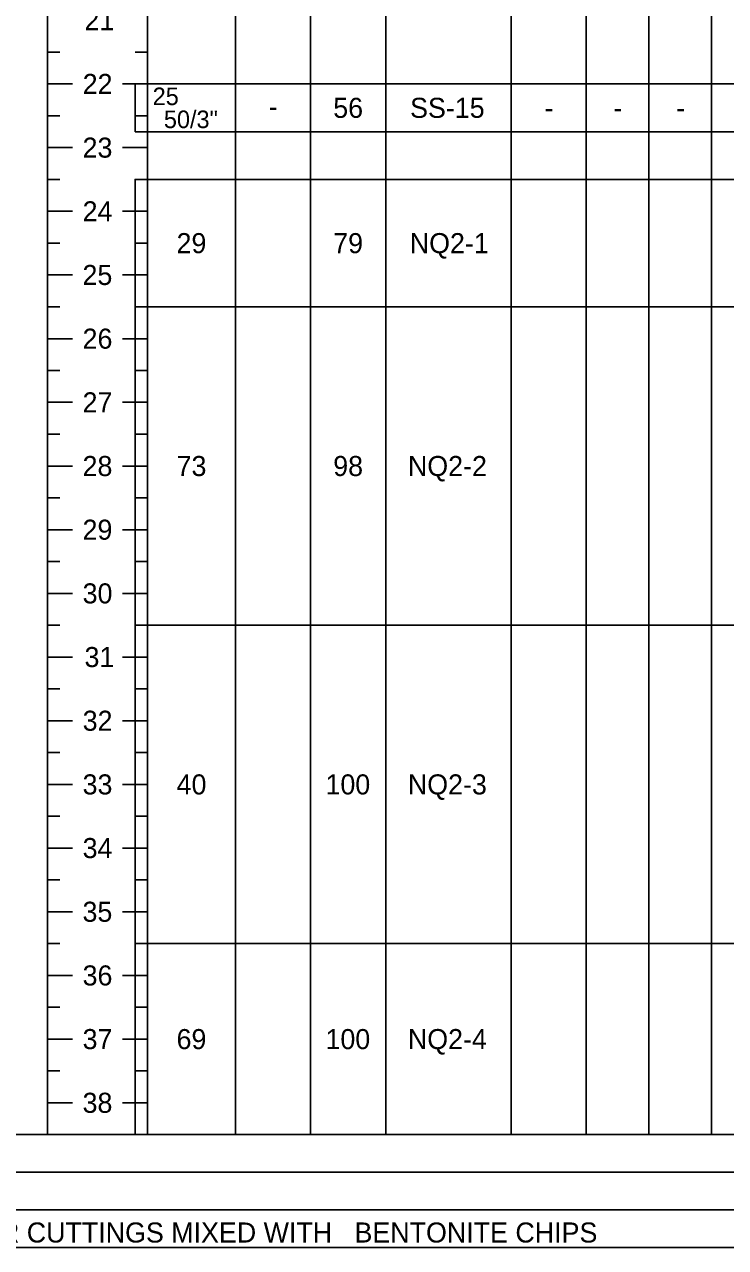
# Model space of a CAD drawing. Extents: x 0 to 0.833, y -0.323 to 0.608.
# Drawn here: x 0.3715 to 0.6046, y -0.3233 to 0.0833 of the extents above; entities that cross this region are included whole.
import ezdxf

# ---------------------------------------------------------------- set-up
doc = ezdxf.new("R2010")
doc.units = 0

msp = doc.modelspace()

# ---------------------------------------------------------------- linework, layer by layer
for points in [[(0, -0.32328), (0.83333, -0.32328), (0.83333, 0.60833), (0, 0.60833)], [(0.40833, 0.04762), (0.4125, 0.04762), (0.4125, 0.0635), (0.40833, 0.0635)], [(0.40833, -0.01058), (0.4125, -0.01058), (0.4125, 0.03175), (0.40833, 0.03175)], [(0.40833, -0.11642), (0.4125, -0.11642), (0.4125, -0.01058), (0.40833, -0.01058)], [(0.40833, -0.22225), (0.4125, -0.22225), (0.4125, -0.11642), (0.40833, -0.11642)], [(0.40833, -0.28575), (0.4125, -0.28575), (0.4125, -0.22225), (0.40833, -0.22225)]]:
    msp.add_lwpolyline(points, close=True)
for points in [[(0.4125, 0.55417), (0.4125, -0.28575)], [(0.4125, 0.55417), (0.4125, -0.28575)], [(0.44167, 0.55417), (0.44167, -0.28575)], [(0.46667, 0.55417), (0.46667, -0.28575)], [(0.49167, 0.55417), (0.49167, -0.28575)], [(0.53333, 0.55417), (0.53333, -0.28575)], [(0.55833, 0.55417), (0.55833, -0.28575)], [(0.57917, 0.54167), (0.57917, -0.28575)], [(0.6, 0.54167), (0.6, -0.28575)], [(0.37917, 0.52917), (0.37917, -0.28575)], [(0.37917, 0.07408), (0.38333, 0.07408)], [(0.4125, 0.07408), (0.40833, 0.07408)], [(0.37917, 0.0635), (0.3875, 0.0635)], [(0.37917, 0.0635), (0.38333, 0.0635)], [(0.4125, 0.0635), (0.40417, 0.0635)], [(0.40833, 0.0635), (0.40833, 0.04762)], [(0.40833, 0.0635), (0.4125, 0.0635)], [(0.4125, 0.0635), (0.40833, 0.0635)], [(0.4125, 0.0635), (0.44167, 0.0635)], [(0.44167, 0.0635), (0.46667, 0.0635)], [(0.46667, 0.0635), (0.49167, 0.0635)], [(0.49167, 0.0635), (0.53333, 0.0635)], [(0.53333, 0.0635), (0.55833, 0.0635)], [(0.55833, 0.0635), (0.57917, 0.0635)], [(0.57917, 0.0635), (0.6, 0.0635)], [(0.6, 0.0635), (0.62083, 0.0635)], [(0.37917, 0.05292), (0.38333, 0.05292)], [(0.4125, 0.05292), (0.40833, 0.05292)], [(0.40833, 0.04762), (0.4125, 0.04762)], [(0.4125, 0.04762), (0.44167, 0.04762)], [(0.44167, 0.04762), (0.46667, 0.04762)], [(0.46667, 0.04762), (0.49167, 0.04762)], [(0.49167, 0.04762), (0.53333, 0.04762)], [(0.53333, 0.04762), (0.55833, 0.04762)], [(0.55833, 0.04762), (0.57917, 0.04762)], [(0.57917, 0.04762), (0.6, 0.04762)], [(0.6, 0.04762), (0.62083, 0.04762)], [(0.37917, 0.04233), (0.3875, 0.04233)], [(0.37917, 0.04233), (0.38333, 0.04233)], [(0.4125, 0.04233), (0.40417, 0.04233)], [(0.4125, 0.04233), (0.40833, 0.04233)], [(0.37917, 0.03175), (0.38333, 0.03175)], [(0.40833, 0.03175), (0.40833, -0.01058)], [(0.40833, 0.03175), (0.4125, 0.03175)], [(0.4125, 0.03175), (0.40833, 0.03175)], [(0.4125, 0.03175), (0.44167, 0.03175)], [(0.44167, 0.03175), (0.46667, 0.03175)], [(0.46667, 0.03175), (0.49167, 0.03175)], [(0.49167, 0.03175), (0.53333, 0.03175)], [(0.53333, 0.03175), (0.55833, 0.03175)], [(0.55833, 0.03175), (0.57917, 0.03175)], [(0.57917, 0.03175), (0.6, 0.03175)], [(0.6, 0.03175), (0.62083, 0.03175)], [(0.37917, 0.02117), (0.3875, 0.02117)], [(0.37917, 0.02117), (0.38333, 0.02117)], [(0.4125, 0.02117), (0.40417, 0.02117)], [(0.4125, 0.02117), (0.40833, 0.02117)], [(0.37917, 0.01058), (0.38333, 0.01058)], [(0.4125, 0.01058), (0.40833, 0.01058)], [(0.37917, 0), (0.3875, 0)], [(0.37917, 0), (0.38333, 0)], [(0.4125, 0), (0.40417, 0)], [(0.4125, 0), (0.40833, 0)], [(0.37917, -0.01058), (0.38333, -0.01058)], [(0.40833, -0.01058), (0.4125, -0.01058)], [(0.40833, -0.01058), (0.40833, -0.11642)], [(0.40833, -0.01058), (0.4125, -0.01058)], [(0.4125, -0.01058), (0.40833, -0.01058)], [(0.4125, -0.01058), (0.44167, -0.01058)], [(0.44167, -0.01058), (0.46667, -0.01058)], [(0.46667, -0.01058), (0.49167, -0.01058)], [(0.49167, -0.01058), (0.53333, -0.01058)], [(0.53333, -0.01058), (0.55833, -0.01058)], [(0.55833, -0.01058), (0.57917, -0.01058)], [(0.57917, -0.01058), (0.6, -0.01058)], [(0.6, -0.01058), (0.62083, -0.01058)], [(0.37917, -0.02117), (0.3875, -0.02117)], [(0.37917, -0.02117), (0.38333, -0.02117)], [(0.4125, -0.02117), (0.40417, -0.02117)], [(0.4125, -0.02117), (0.40833, -0.02117)], [(0.37917, -0.03175), (0.38333, -0.03175)], [(0.4125, -0.03175), (0.40833, -0.03175)], [(0.37917, -0.04233), (0.3875, -0.04233)], [(0.37917, -0.04233), (0.38333, -0.04233)], [(0.4125, -0.04233), (0.40417, -0.04233)], [(0.4125, -0.04233), (0.40833, -0.04233)], [(0.37917, -0.05292), (0.38333, -0.05292)], [(0.4125, -0.05292), (0.40833, -0.05292)], [(0.37917, -0.0635), (0.3875, -0.0635)], [(0.37917, -0.0635), (0.38333, -0.0635)], [(0.4125, -0.0635), (0.40417, -0.0635)], [(0.4125, -0.0635), (0.40833, -0.0635)], [(0.37917, -0.07408), (0.38333, -0.07408)], [(0.4125, -0.07408), (0.40833, -0.07408)], [(0.37917, -0.08467), (0.3875, -0.08467)], [(0.37917, -0.08467), (0.38333, -0.08467)], [(0.4125, -0.08467), (0.40417, -0.08467)], [(0.4125, -0.08467), (0.40833, -0.08467)], [(0.37917, -0.09525), (0.38333, -0.09525)], [(0.4125, -0.09525), (0.40833, -0.09525)], [(0.37917, -0.10583), (0.3875, -0.10583)], [(0.37917, -0.10583), (0.38333, -0.10583)], [(0.4125, -0.10583), (0.40417, -0.10583)], [(0.4125, -0.10583), (0.40833, -0.10583)], [(0.37917, -0.11642), (0.38333, -0.11642)], [(0.40833, -0.11642), (0.4125, -0.11642)], [(0.40833, -0.11642), (0.40833, -0.22225)], [(0.40833, -0.11642), (0.4125, -0.11642)], [(0.4125, -0.11642), (0.40833, -0.11642)], [(0.4125, -0.11642), (0.44167, -0.11642)], [(0.44167, -0.11642), (0.46667, -0.11642)], [(0.46667, -0.11642), (0.49167, -0.11642)], [(0.49167, -0.11642), (0.53333, -0.11642)], [(0.53333, -0.11642), (0.55833, -0.11642)], [(0.55833, -0.11642), (0.57917, -0.11642)], [(0.57917, -0.11642), (0.6, -0.11642)], [(0.6, -0.11642), (0.62083, -0.11642)], [(0.37917, -0.127), (0.3875, -0.127)], [(0.37917, -0.127), (0.38333, -0.127)], [(0.4125, -0.127), (0.40417, -0.127)], [(0.4125, -0.127), (0.40833, -0.127)], [(0.37917, -0.13758), (0.38333, -0.13758)], [(0.4125, -0.13758), (0.40833, -0.13758)], [(0.37917, -0.14817), (0.3875, -0.14817)], [(0.37917, -0.14817), (0.38333, -0.14817)], [(0.4125, -0.14817), (0.40417, -0.14817)], [(0.4125, -0.14817), (0.40833, -0.14817)], [(0.37917, -0.15875), (0.38333, -0.15875)], [(0.4125, -0.15875), (0.40833, -0.15875)], [(0.37917, -0.16933), (0.3875, -0.16933)], [(0.37917, -0.16933), (0.38333, -0.16933)], [(0.4125, -0.16933), (0.40417, -0.16933)], [(0.4125, -0.16933), (0.40833, -0.16933)], [(0.37917, -0.17992), (0.38333, -0.17992)], [(0.4125, -0.17992), (0.40833, -0.17992)], [(0.37917, -0.1905), (0.3875, -0.1905)], [(0.37917, -0.1905), (0.38333, -0.1905)], [(0.4125, -0.1905), (0.40417, -0.1905)], [(0.4125, -0.1905), (0.40833, -0.1905)], [(0.37917, -0.20108), (0.38333, -0.20108)], [(0.4125, -0.20108), (0.40833, -0.20108)], [(0, -0.21078), (0, -0.32328), (0.83333, -0.32328), (0.83333, -0.21078)], [(0.37917, -0.21167), (0.3875, -0.21167)], [(0.37917, -0.21167), (0.38333, -0.21167)], [(0.4125, -0.21167), (0.40417, -0.21167)], [(0.4125, -0.21167), (0.40833, -0.21167)], [(0.37917, -0.22225), (0.38333, -0.22225)], [(0.40833, -0.22225), (0.4125, -0.22225)], [(0.40833, -0.22225), (0.40833, -0.28575)], [(0.40833, -0.22225), (0.4125, -0.22225)], [(0.4125, -0.22225), (0.40833, -0.22225)], [(0.4125, -0.22225), (0.44167, -0.22225)], [(0.44167, -0.22225), (0.46667, -0.22225)], [(0.46667, -0.22225), (0.49167, -0.22225)], [(0.49167, -0.22225), (0.53333, -0.22225)], [(0.53333, -0.22225), (0.55833, -0.22225)], [(0.55833, -0.22225), (0.57917, -0.22225)], [(0.57917, -0.22225), (0.6, -0.22225)], [(0.6, -0.22225), (0.62083, -0.22225)], [(0.37917, -0.23283), (0.3875, -0.23283)], [(0.37917, -0.23283), (0.38333, -0.23283)], [(0.4125, -0.23283), (0.40417, -0.23283)], [(0.4125, -0.23283), (0.40833, -0.23283)], [(0.37917, -0.24342), (0.38333, -0.24342)], [(0.4125, -0.24342), (0.40833, -0.24342)], [(0.37917, -0.254), (0.3875, -0.254)], [(0.37917, -0.254), (0.38333, -0.254)], [(0.4125, -0.254), (0.40417, -0.254)], [(0.4125, -0.254), (0.40833, -0.254)], [(0.37917, -0.26458), (0.38333, -0.26458)], [(0.4125, -0.26458), (0.40833, -0.26458)], [(0.37917, -0.27517), (0.3875, -0.27517)], [(0.37917, -0.27517), (0.38333, -0.27517)], [(0.4125, -0.27517), (0.40417, -0.27517)], [(0.4125, -0.27517), (0.40833, -0.27517)], [(0.33333, -0.28575), (0.37917, -0.28575)], [(0.37917, -0.28575), (0.4125, -0.28575)], [(0.37917, -0.28575), (0.38333, -0.28575)], [(0.37917, -0.28575), (0.39583, -0.28575)], [(0.4125, -0.28575), (0.39583, -0.28575)], [(0.40833, -0.28575), (0.4125, -0.28575)], [(0.40833, -0.28575), (0.4125, -0.28575)], [(0.4125, -0.28575), (0.40833, -0.28575)], [(0.4125, -0.28575), (0.44167, -0.28575)], [(0.44167, -0.28575), (0.46667, -0.28575)], [(0.46667, -0.28575), (0.49167, -0.28575)], [(0.49167, -0.28575), (0.53333, -0.28575)], [(0.53333, -0.28575), (0.55833, -0.28575)], [(0.55833, -0.28575), (0.57917, -0.28575)], [(0.57917, -0.28575), (0.6, -0.28575)], [(0.6, -0.28575), (0.62083, -0.28575)], [(0, -0.29828), (0.83333, -0.29828)], [(0, -0.31078), (0.83333, -0.31078)]]:
    msp.add_lwpolyline(points)

# ---------------------------------------------------------------- texts
for s, height, p in [('21', 0.006667, (0.39151, 0.08133)), ('22', 0.006667, (0.3909, 0.06017)), ('25', 0.005833, (0.41417, 0.05647)), ('56', 0.006667, (0.4742, 0.05223)), ('SS-15', 0.006667, (0.49974, 0.05223)), ('50/3"', 0.005833, (0.4179, 0.04882)), ('-', 0.00667, (0.45276, 0.05265)), ('-', 0.00667, (0.54443, 0.05223)), ('-', 0.00667, (0.56734, 0.05223)), ('-', 0.00667, (0.58818, 0.05223)), ('23', 0.006667, (0.39087, 0.039)), ('24', 0.006667, (0.39088, 0.01783)), ('29', 0.006667, (0.42211, 0.00725)), ('79', 0.006667, (0.47419, 0.00725)), ('NQ2-1', 0.006667, (0.49964, 0.00725)), ('25', 0.006667, (0.39084, -0.00333)), ('26', 0.006667, (0.39087, -0.0245)), ('27', 0.006667, (0.39087, -0.04567)), ('28', 0.006667, (0.39086, -0.06683)), ('73', 0.006667, (0.42212, -0.06683)), ('98', 0.006667, (0.47419, -0.06683)), ('NQ2-2', 0.006667, (0.49903, -0.06683)), ('29', 0.006667, (0.39086, -0.088)), ('30', 0.006667, (0.39088, -0.10917)), ('31', 0.006667, (0.39151, -0.13033)), ('32', 0.006667, (0.3909, -0.1515)), ('33', 0.006667, (0.39087, -0.17267)), ('40', 0.006667, (0.42213, -0.17267)), ('100', 0.006667, (0.47162, -0.17267)), ('NQ2-3', 0.006667, (0.499, -0.17267)), ('34', 0.006667, (0.39088, -0.19383)), ('35', 0.006667, (0.39084, -0.215)), ('36', 0.006667, (0.39087, -0.23617)), ('37', 0.006667, (0.39087, -0.25733)), ('69', 0.006667, (0.42211, -0.25733)), ('100', 0.006667, (0.47162, -0.25733)), ('NQ2-4', 0.006667, (0.49901, -0.25733)), ('38', 0.006667, (0.39086, -0.2785)), ('ASPHALT PATCH; AUGER CUTTINGS MIXED WITH   BENTONITE CHIPS', 0.0066667, (0.25986, -0.32162))]:
    msp.add_text(s, height=height).set_placement(p)

doc.saveas('drawing.dxf')
